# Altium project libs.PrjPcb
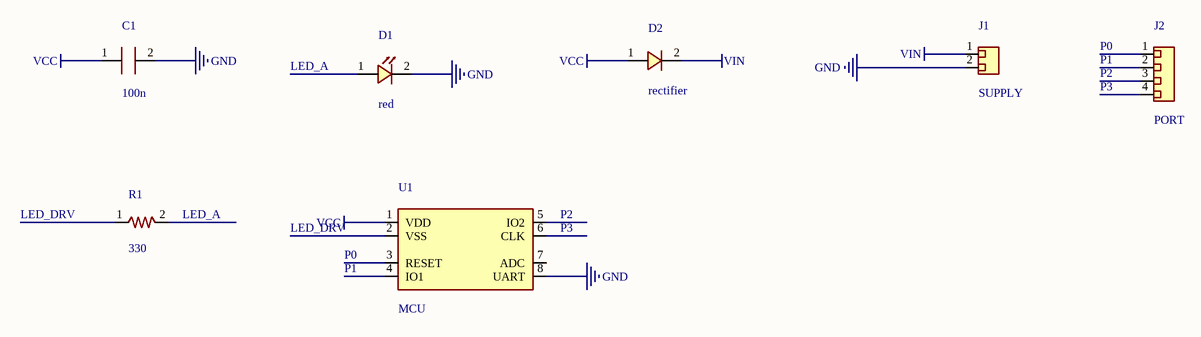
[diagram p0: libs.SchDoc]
1 sheet, 7 parts. Net scope: global (net labels, ports and power ports of the same name join across sheets).
Board file: libs.PcbDoc

## Sheet libs.SchDoc
size A4

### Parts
C1  100n  [Chip_0805]
D1  red  [LED0603_Kingbright_APT1608SURCK]
D2  rectifier  [DO214AC]
J1  SUPPLY  [Header_1x2_P2.54]
J2  PORT  [Header_1x4_P2.54]
R1  330  [Chip_0603]
U1  MCU  [DIP8_Microchip_P]

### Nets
GND: C1.2(B) D1.2(K) J1.2(Passive) U1.8(UART)
VCC: C1.1(A) D2.1(A) U1.1(VDD)
VIN: D2.2(K) J1.1(Passive)
LED_A: D1.1(A) R1.2(B)
LED_DRV: R1.1(A) U1.2(VSS)
P0: J2.1(Passive) U1.3(RESET)
P1: J2.2(Passive) U1.4(IO1)
P2: J2.3(Passive) U1.5(IO2)
P3: J2.4(Passive) U1.6(CLK)

Not connected (* = marked no-connect by the designer): U1 7(ADC)

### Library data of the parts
C1 = Capacitor
D1 = LED: pin to pad: 1>2 2>1
D2 = Diode
J1 = Connector_2
J2 = Connector_4
R1 = Resistor
U1 = Microcontroller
